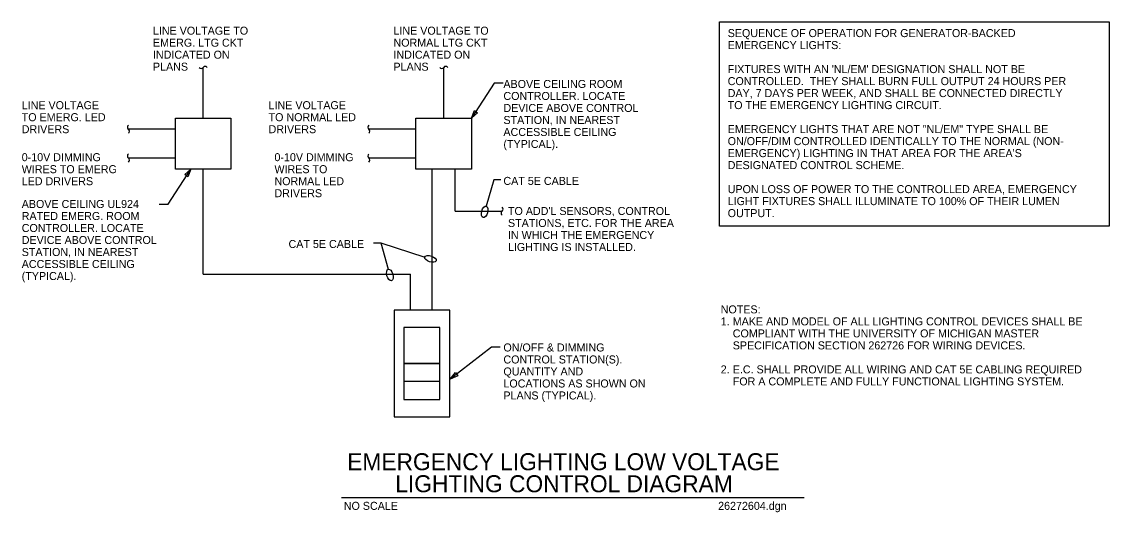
# Model space of a CAD drawing. Extents: x 10015.3 to 10105.8, y 10142.3 to 10183.2.
import ezdxf

# ---------------------------------------------------------------- set-up
doc = ezdxf.new("R2010")
doc.units = 0
for name, color, linetype in [('G-ANNO-CELL', 7, 'Continuous'), ('G-ANNO-TEXT', 7, 'Continuous'), ('G-DETL-LINE', 7, 'Continuous'), ('Level 3', 7, 'Continuous')]:
    doc.layers.add(name, color=color, linetype=linetype)

msp = doc.modelspace()

# ---------------------------------------------------------------- linework, layer by layer
at = {"layer": 'G-ANNO-CELL'}
msp.add_line((10041.898, 10143.523), (10080.422, 10143.523), dxfattribs=at)
at = {"layer": 'G-ANNO-TEXT'}
msp.add_line((10045.16, 10164.725), (10048.816, 10163.547), dxfattribs=at)
for points in [[(10073.359, 10183.155), (10105.82, 10183.155), (10105.82, 10166.13), (10073.359, 10166.13)], [(10053.226, 10175.576), (10052.712, 10175.12), (10052.95, 10175.764)], [(10028.828, 10170.419), (10029.341, 10170.876), (10029.103, 10170.231)], [(10051.572, 10153.663), (10050.944, 10153.384), (10051.367, 10153.926)]]:
    msp.add_lwpolyline(points, close=True, dxfattribs=at)
for points in [[(10055.339, 10178.027), (10054.61, 10178.027), (10052.712, 10175.12)], [(10026.714, 10167.968), (10027.443, 10167.968), (10029.341, 10170.876)], [(10055.165, 10169.982), (10054.564, 10169.982), (10053.944, 10167.794)], [(10044.558, 10164.725), (10045.16, 10164.725), (10045.779, 10162.537)], [(10055.113, 10156.042), (10054.384, 10156.042), (10050.944, 10153.384)]]:
    msp.add_lwpolyline(points, dxfattribs=at)
for centre, major_axis in [((10053.808, 10167.313), (-0.136, -0.481)), ((10049.292, 10163.393), (0.476, -0.153)), ((10045.915, 10162.056), (0.136, -0.481))]:
    msp.add_ellipse(centre, major_axis=major_axis, ratio=0.5, dxfattribs=at)
at = {"layer": 'G-DETL-LINE'}
for p, q in [((10030.367, 10175.12), (10030.367, 10179.355)), ((10050.396, 10175.12), (10050.396, 10179.355)), ((10028.051, 10174.196), (10024.137, 10174.196)), ((10048.08, 10174.196), (10044.166, 10174.196)), ((10028.051, 10171.799), (10024.137, 10171.799)), ((10048.08, 10171.799), (10044.166, 10171.799)), ((10030.367, 10162.119), (10030.367, 10170.876)), ((10049.447, 10159.113), (10049.447, 10170.876)), ((10051.345, 10167.375), (10051.345, 10170.876)), ((10051.345, 10167.375), (10055.258, 10167.375)), ((10030.367, 10162.119), (10047.637, 10162.119)), ((10047.637, 10159.113), (10047.637, 10162.119)), ((10050.086, 10153.175), (10047.086, 10153.175))]:
    msp.add_line(p, q, dxfattribs=at)
for points in [[(10028.051, 10175.12), (10032.683, 10175.12), (10032.683, 10170.876), (10028.051, 10170.876)], [(10048.08, 10175.12), (10052.712, 10175.12), (10052.712, 10170.876), (10048.08, 10170.876)], [(10050.902, 10159.113), (10046.27, 10159.113), (10046.27, 10150.237), (10050.902, 10150.237)], [(10050.086, 10157.675), (10047.086, 10157.675), (10047.086, 10154.675), (10050.086, 10154.675)], [(10050.086, 10154.675), (10047.086, 10154.675), (10047.086, 10151.675), (10050.086, 10151.675)]]:
    msp.add_lwpolyline(points, close=True, dxfattribs=at)
for centre, start, end in [((10030.2, 10179.48), 216.8699, 323.1301), ((10030.534, 10179.23), 36.8699, 143.1301), ((10050.229, 10179.48), 216.8699, 323.1301), ((10050.563, 10179.23), 36.8699, 143.1301), ((10024.262, 10174.363), 126.8699, 233.1301), ((10044.291, 10174.363), 126.8699, 233.1301), ((10024.012, 10174.03), 306.8699, 53.1301), ((10044.041, 10174.03), 306.8699, 53.1301), ((10024.262, 10171.966), 126.8699, 233.1301), ((10024.012, 10171.632), 306.8699, 53.1301), ((10044.291, 10171.966), 126.8699, 233.1301), ((10044.041, 10171.632), 306.8699, 53.1301), ((10055.383, 10167.209), 126.8699, 233.1301), ((10055.133, 10167.542), 306.8699, 53.1301)]:
    msp.add_arc(centre, 0.208, start, end, dxfattribs=at)

# ---------------------------------------------------------------- texts
at = {"layer": 'G-ANNO-CELL'}
for s, height, p in [('EMERGENCY LIGHTING LOW VOLTAGE', 1.41667, (10042.364, 10145.789)), ('LIGHTING CONTROL DIAGRAM', 1.41667, (10046.365, 10143.955)), ('NO SCALE', 0.6667, (10042.078, 10142.488))]:
    msp.add_text(s, height=height, dxfattribs=at).set_placement(p)
at = {"layer": 'G-ANNO-TEXT'}
for s, height, p in [('LINE VOLTAGE TO ', 0.66667, (10026.186, 10182.077)), ('LINE VOLTAGE TO ', 0.66667, (10046.215, 10182.077)), ('SEQUENCE OF OPERATION FOR GENERATOR-BACKED ', 0.66667, (10074.046, 10181.876)), ('EMERG. LTG CKT ', 0.66667, (10026.186, 10181.077)), ('NORMAL LTG CKT ', 0.66667, (10046.215, 10181.077)), ('EMERGENCY LIGHTS:', 0.66667, (10074.046, 10180.876)), ('INDICATED ON ', 0.66667, (10026.186, 10180.077)), ('INDICATED ON ', 0.66667, (10046.215, 10180.077)), ('PLANS', 0.6667, (10026.186, 10179.077)), ('PLANS', 0.6667, (10046.215, 10179.077)), ("FIXTURES WITH AN 'NL/EM' DESIGNATION SHALL NOT BE ", 0.66667, (10074.046, 10178.876)), ('ABOVE CEILING ROOM ', 0.66667, (10055.371, 10177.638)), ('CONTROLLED.  THEY SHALL BURN FULL OUTPUT 24 HOURS PER ', 0.66667, (10074.046, 10177.876)), ('CONTROLLER. LOCATE ', 0.66667, (10055.371, 10176.638)), ('DAY, 7 DAYS PER WEEK, AND SHALL BE CONNECTED DIRECTLY ', 0.66667, (10074.046, 10176.876)), ('LINE VOLTAGE ', 0.66667, (10015.259, 10175.869)), ('LINE VOLTAGE ', 0.66667, (10035.814, 10175.869)), ('DEVICE ABOVE CONTROL ', 0.66667, (10055.371, 10175.638)), ('TO THE EMERGENCY LIGHTING CIRCUIT.', 0.66667, (10074.046, 10175.876)), ('TO EMERG. LED ', 0.66667, (10015.259, 10174.869)), ('TO NORMAL LED ', 0.66667, (10035.814, 10174.869)), ('STATION, IN NEAREST ', 0.66667, (10055.371, 10174.638)), ('DRIVERS', 0.6667, (10015.259, 10173.869)), ('DRIVERS', 0.6667, (10035.814, 10173.869)), ('ACCESSIBLE CEILING ', 0.66667, (10055.371, 10173.638)), ('EMERGENCY LIGHTS THAT ARE NOT "NL/EM" TYPE SHALL BE ', 0.66667, (10074.046, 10173.876)), ('ON/OFF/DIM CONTROLLED IDENTICALLY TO THE NORMAL (NON-', 0.66667, (10074.046, 10172.876)), ('(TYPICAL).', 0.6667, (10055.371, 10172.638)), ("EMERGENCY) LIGHTING IN THAT AREA FOR THE AREA'S ", 0.66667, (10074.046, 10171.876)), ('0-10V DIMMING ', 0.66667, (10015.259, 10171.537)), ('0-10V DIMMING ', 0.66667, (10036.304, 10171.537)), ('WIRES TO EMERG ', 0.66667, (10015.259, 10170.537)), ('WIRES TO ', 0.6667, (10036.304, 10170.537)), ('DESIGNATED CONTROL SCHEME.', 0.66667, (10074.046, 10170.876)), ('LED DRIVERS', 0.66667, (10015.259, 10169.537)), ('NORMAL LED ', 0.66667, (10036.304, 10169.537)), ('CAT 5E CABLE', 0.66667, (10055.371, 10169.56)), ('DRIVERS', 0.6667, (10036.304, 10168.537)), ('UPON LOSS OF POWER TO THE CONTROLLED AREA, EMERGENCY ', 0.66667, (10074.046, 10168.876)), ('ABOVE CEILING UL924 ', 0.66667, (10015.259, 10167.637)), ('LIGHT FIXTURES SHALL ILLUMINATE TO 100% OF THEIR LUMEN ', 0.66667, (10074.046, 10167.876)), ('RATED EMERG. ROOM ', 0.66667, (10015.259, 10166.637)), ("TO ADD'L SENSORS, CONTROL ", 0.66667, (10055.749, 10167.055)), ('OUTPUT.', 0.6667, (10074.046, 10166.876)), ('CONTROLLER. LOCATE ', 0.66667, (10015.259, 10165.637)), ('STATIONS, ETC. FOR THE AREA ', 0.66667, (10055.749, 10166.055)), ('DEVICE ABOVE CONTROL ', 0.66667, (10015.259, 10164.637)), ('IN WHICH THE EMERGENCY ', 0.66667, (10055.749, 10165.055)), ('CAT 5E CABLE', 0.66667, (10037.478, 10164.304)), ('LIGHTING IS INSTALLED.', 0.66667, (10055.749, 10164.055)), ('STATION, IN NEAREST ', 0.66667, (10015.259, 10163.637)), ('ACCESSIBLE CEILING ', 0.66667, (10015.259, 10162.637)), ('(TYPICAL).', 0.6667, (10015.259, 10161.637)), ('NOTES:', 0.6667, (10073.466, 10158.856)), ('1.', 0.6667, (10073.466, 10157.856)), ('MAKE AND MODEL OF ALL LIGHTING CONTROL DEVICES SHALL BE ', 0.66667, (10074.468, 10157.856)), ('COMPLIANT WITH THE UNIVERSITY OF MICHIGAN MASTER ', 0.66667, (10074.468, 10156.856)), ('ON/OFF & DIMMING ', 0.66667, (10055.371, 10155.683)), ('SPECIFICATION SECTION 262726 FOR WIRING DEVICES.', 0.66667, (10074.468, 10155.856)), ('CONTROL STATION(S). ', 0.66667, (10055.371, 10154.683)), ('2.', 0.6667, (10073.466, 10153.856)), ('E.C. SHALL PROVIDE ALL WIRING AND CAT 5E CABLING REQUIRED ', 0.66667, (10074.468, 10153.856)), ('QUANTITY AND ', 0.66667, (10055.371, 10153.683)), ('FOR A COMPLETE AND FULLY FUNCTIONAL LIGHTING SYSTEM.', 0.66667, (10074.468, 10152.856)), ('LOCATIONS AS SHOWN ON ', 0.66667, (10055.371, 10152.683)), ('PLANS (TYPICAL).', 0.66667, (10055.371, 10151.683))]:
    msp.add_text(s, height=height, dxfattribs=at).set_placement(p)
at = {"layer": 'Level 3'}
msp.add_text('26272604.dgn', height=0.66667, dxfattribs=at).set_placement((10073.251, 10142.488))

doc.saveas('drawing.dxf')
